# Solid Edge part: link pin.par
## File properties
Author: Deepak Maini
Template: Normal.par
Last saved by: Robert a Rhodes jr
Revision: 5
Application: Solid Edge
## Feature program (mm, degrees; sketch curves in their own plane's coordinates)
sketch for "unnamed RevolvedProtrusion 1" plane through (0, 0, 0) normal (0, -1, 0) x-axis (1, 0, 0)
  line (0, 27.2464) -> (7.5, 27.2464)
  line (7.5, 27.2464) -> (7.5, 20.2464)
  line (7.5, 20.2464) -> (5, 20.2464)
  line (5, 20.2464) -> (5, -22.7536)
  line (5, -22.7536) -> (0, -22.7536)
  line (0, -22.7536) -> (0, 27.2464)
revolve "unnamed RevolvedProtrusion 1" add finite 360 deg
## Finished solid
Body 1: solid body, 5 faces, 4 edges, 0 vertices.
  Faces by surface: plane 3, cylinder 2
  Edges by curve: circle 4
Bounding box of the edges (mm): 15.000 x 15.000 x 50.000, from (-7.5, -7.5, -22.7536) to (7.5, 7.5, 27.2464).
Cylindrical faces by radius (mm): R5 x1, R7.5 x1
Planar faces by outward normal: +z 1, -z 2
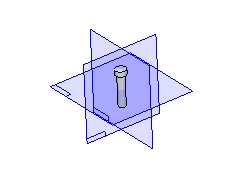
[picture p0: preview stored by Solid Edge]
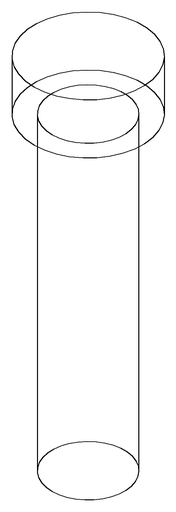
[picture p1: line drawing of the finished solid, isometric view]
